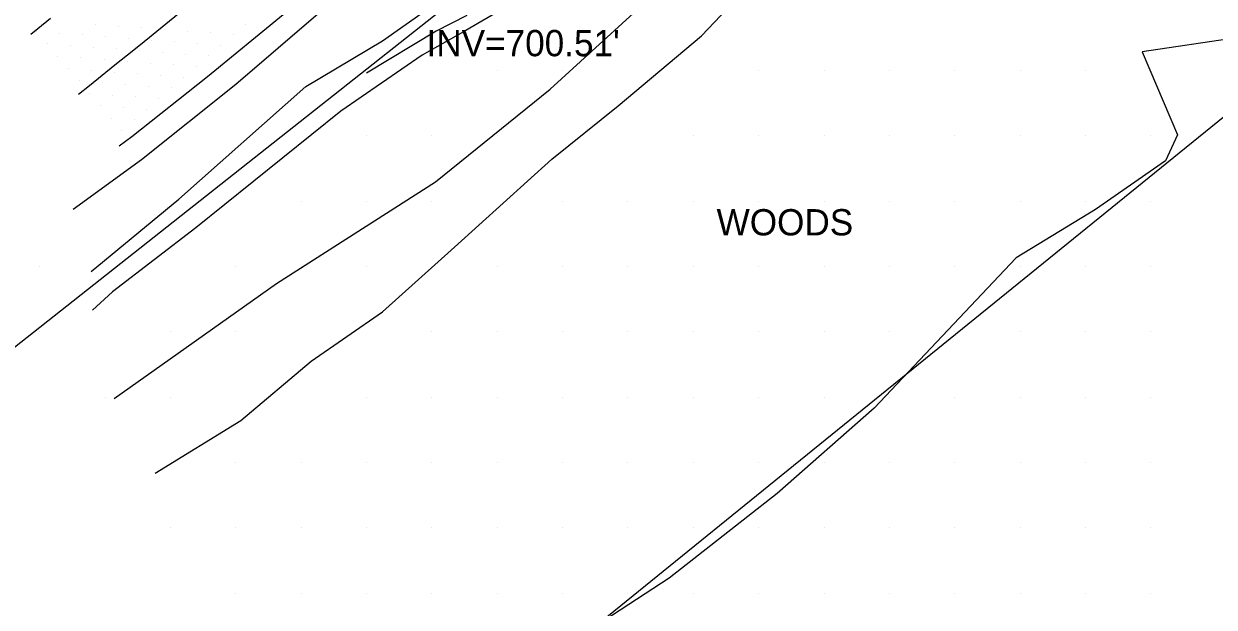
# Model space of a CAD drawing. Extents: x 1548934 to 1561348, y 809680 to 824075.
# Drawn here: x 1551457.5 to 1551639.7, y 810277.8 to 810367.1 of the extents above; entities that cross this region are included whole.
import ezdxf

# ---------------------------------------------------------------- set-up
doc = ezdxf.new("R2010")
doc.units = 0
for name, color, linetype in [('E_NCDOT_Vertical_Profile_Ground_Line', 7, 'Continuous'), ('Exist DTM QL2 LIDAR Elevation Point', 7, 'Continuous'), ('Exist DTM Scan Elevation Point', 7, 'Continuous'), ('Exist Structure Minor Pipes RCP 24 Inch Invert Elevation', 7, 'Continuous'), ('Exist Vegetation Woods Line', 7, 'Continuous'), ('Exist Vegetation Woods Line Text', 7, 'Continuous'), ('P_RDY_Dimension_Text', 7, 'Continuous'), ('P_RDY_Lane_Line', 7, 'Continuous'), ('P_RDY_Terminator_Cell', 7, 'Continuous'), ('PH Exist DTM Breakline', 7, 'Continuous')]:
    doc.layers.add(name, color=color, linetype=linetype)

msp = doc.modelspace()

# ---------------------------------------------------------------- linework, layer by layer
at = {"layer": 'E_NCDOT_Vertical_Profile_Ground_Line'}
msp.add_lwpolyline([(1551472.11, 810348.46), (1551474.03, 810349.86), (1551485.64, 810359.04), (1551508.8, 810378.11), (1551532.17, 810396.94), (1551555.37, 810415.98), (1551578.48, 810435.11), (1551601.47, 810454.39), (1551624.77, 810473.31), (1551647.83, 810492.49), (1551655.17, 810499.15), (1551678.16, 810518.43), (1551701.2, 810537.64), (1551724, 810557.15), (1551746.83, 810576.6), (1551761.53, 810588.98)], dxfattribs=at)
at = {"layer": 'Exist DTM QL2 LIDAR Elevation Point'}
for p, q in [((1551529.98, 810359.96), (1551529.98, 810359.96)), ((1551539.98, 810359.96), (1551539.98, 810359.96)), ((1551569.98, 810359.96), (1551569.98, 810359.96)), ((1551579.99, 810359.96), (1551579.99, 810359.96)), ((1551589.99, 810359.96), (1551589.99, 810359.96)), ((1551599.99, 810359.96), (1551599.99, 810359.96)), ((1551609.99, 810359.96), (1551609.99, 810359.96)), ((1551619.99, 810359.96), (1551619.99, 810359.96)), ((1551629.99, 810359.96), (1551629.99, 810359.96)), ((1551509.98, 810349.96), (1551509.98, 810349.96)), ((1551519.98, 810349.96), (1551519.98, 810349.96)), ((1551529.98, 810349.96), (1551529.98, 810349.96)), ((1551559.98, 810349.96), (1551559.98, 810349.96)), ((1551569.98, 810349.96), (1551569.98, 810349.96)), ((1551579.99, 810349.96), (1551579.99, 810349.96)), ((1551589.99, 810349.96), (1551589.99, 810349.96)), ((1551599.99, 810349.96), (1551599.99, 810349.96)), ((1551609.99, 810349.96), (1551609.99, 810349.96)), ((1551619.99, 810349.96), (1551619.99, 810349.96)), ((1551629.99, 810349.96), (1551629.99, 810349.96)), ((1551499.98, 810339.96), (1551499.98, 810339.96)), ((1551509.98, 810339.96), (1551509.98, 810339.96)), ((1551519.98, 810339.96), (1551519.98, 810339.96)), ((1551539.98, 810339.96), (1551539.98, 810339.96)), ((1551549.98, 810339.96), (1551549.98, 810339.96)), ((1551559.98, 810339.96), (1551559.98, 810339.96)), ((1551569.98, 810339.96), (1551569.98, 810339.96)), ((1551579.99, 810339.96), (1551579.99, 810339.96)), ((1551589.99, 810339.96), (1551589.99, 810339.96)), ((1551599.99, 810339.96), (1551599.99, 810339.96)), ((1551609.99, 810339.96), (1551609.99, 810339.96)), ((1551619.99, 810339.96), (1551619.99, 810339.96)), ((1551629.99, 810339.96), (1551629.99, 810339.96)), ((1551459.98, 810329.96), (1551459.98, 810329.96)), ((1551489.98, 810329.96), (1551489.98, 810329.96)), ((1551499.98, 810329.96), (1551499.98, 810329.96)), ((1551509.98, 810329.96), (1551509.98, 810329.96)), ((1551529.98, 810329.96), (1551529.98, 810329.96)), ((1551539.98, 810329.96), (1551539.98, 810329.96)), ((1551549.98, 810329.96), (1551549.98, 810329.96)), ((1551559.98, 810329.96), (1551559.98, 810329.96)), ((1551569.98, 810329.96), (1551569.98, 810329.96)), ((1551579.99, 810329.96), (1551579.99, 810329.96)), ((1551589.99, 810329.96), (1551589.99, 810329.96)), ((1551599.99, 810329.96), (1551599.99, 810329.96)), ((1551609.99, 810329.96), (1551609.99, 810329.96)), ((1551619.99, 810329.96), (1551619.99, 810329.96)), ((1551629.99, 810329.96), (1551629.99, 810329.96)), ((1551459.98, 810319.96), (1551459.98, 810319.96)), ((1551479.98, 810319.96), (1551479.98, 810319.96)), ((1551489.98, 810319.96), (1551489.98, 810319.96)), ((1551519.98, 810319.96), (1551519.98, 810319.96)), ((1551529.98, 810319.96), (1551529.98, 810319.96)), ((1551539.98, 810319.96), (1551539.98, 810319.96)), ((1551549.98, 810319.96), (1551549.98, 810319.96)), ((1551559.98, 810319.96), (1551559.98, 810319.96)), ((1551569.98, 810319.96), (1551569.98, 810319.96)), ((1551579.99, 810319.96), (1551579.99, 810319.96)), ((1551589.99, 810319.96), (1551589.99, 810319.96)), ((1551599.99, 810319.96), (1551599.99, 810319.96)), ((1551609.99, 810319.96), (1551609.99, 810319.96)), ((1551619.99, 810319.96), (1551619.99, 810319.96)), ((1551629.99, 810319.96), (1551629.99, 810319.96)), ((1551469.98, 810309.96), (1551469.98, 810309.96)), ((1551479.98, 810309.96), (1551479.98, 810309.96)), ((1551509.98, 810309.96), (1551509.98, 810309.96)), ((1551519.98, 810309.96), (1551519.98, 810309.96)), ((1551529.98, 810309.96), (1551529.98, 810309.96)), ((1551539.98, 810309.96), (1551539.98, 810309.96)), ((1551549.98, 810309.96), (1551549.98, 810309.96)), ((1551559.98, 810309.96), (1551559.98, 810309.96)), ((1551569.98, 810309.96), (1551569.98, 810309.96)), ((1551579.99, 810309.96), (1551579.99, 810309.96)), ((1551589.99, 810309.96), (1551589.99, 810309.96)), ((1551599.99, 810309.96), (1551599.99, 810309.96)), ((1551609.99, 810309.96), (1551609.99, 810309.96)), ((1551619.99, 810309.96), (1551619.99, 810309.96)), ((1551629.99, 810309.96), (1551629.99, 810309.96)), ((1551489.98, 810299.96), (1551489.98, 810299.96)), ((1551499.98, 810299.96), (1551499.98, 810299.96)), ((1551509.98, 810299.96), (1551509.98, 810299.96)), ((1551519.98, 810299.96), (1551519.98, 810299.96)), ((1551529.98, 810299.96), (1551529.98, 810299.96)), ((1551539.98, 810299.96), (1551539.98, 810299.96)), ((1551549.98, 810299.96), (1551549.98, 810299.96)), ((1551559.98, 810299.96), (1551559.98, 810299.96)), ((1551569.98, 810299.96), (1551569.98, 810299.96)), ((1551579.99, 810299.96), (1551579.99, 810299.96)), ((1551589.99, 810299.96), (1551589.99, 810299.96)), ((1551599.99, 810299.96), (1551599.99, 810299.96)), ((1551609.99, 810299.96), (1551609.99, 810299.96)), ((1551619.99, 810299.96), (1551619.99, 810299.96)), ((1551629.99, 810299.96), (1551629.99, 810299.96)), ((1551479.98, 810289.95), (1551479.98, 810289.95)), ((1551489.98, 810289.95), (1551489.98, 810289.95)), ((1551499.98, 810289.95), (1551499.98, 810289.95)), ((1551509.98, 810289.95), (1551509.98, 810289.95)), ((1551519.98, 810289.95), (1551519.98, 810289.95)), ((1551529.98, 810289.95), (1551529.98, 810289.95)), ((1551539.98, 810289.95), (1551539.98, 810289.95)), ((1551549.98, 810289.95), (1551549.98, 810289.95)), ((1551559.98, 810289.95), (1551559.98, 810289.95)), ((1551569.98, 810289.95), (1551569.98, 810289.95)), ((1551579.99, 810289.95), (1551579.99, 810289.95)), ((1551589.99, 810289.95), (1551589.99, 810289.95)), ((1551599.99, 810289.95), (1551599.99, 810289.95)), ((1551609.99, 810289.95), (1551609.99, 810289.95)), ((1551619.99, 810289.95), (1551619.99, 810289.95)), ((1551629.99, 810289.95), (1551629.99, 810289.95)), ((1551489.98, 810279.95), (1551489.98, 810279.95)), ((1551499.98, 810279.95), (1551499.98, 810279.95)), ((1551509.98, 810279.95), (1551509.98, 810279.95)), ((1551519.98, 810279.95), (1551519.98, 810279.95)), ((1551529.98, 810279.95), (1551529.98, 810279.95)), ((1551539.98, 810279.95), (1551539.98, 810279.95)), ((1551549.98, 810279.95), (1551549.98, 810279.95)), ((1551559.98, 810279.95), (1551559.98, 810279.95)), ((1551569.98, 810279.95), (1551569.98, 810279.95)), ((1551579.99, 810279.95), (1551579.99, 810279.95)), ((1551589.99, 810279.95), (1551589.99, 810279.95)), ((1551599.99, 810279.95), (1551599.99, 810279.95)), ((1551609.99, 810279.95), (1551609.99, 810279.95)), ((1551619.99, 810279.95), (1551619.99, 810279.95)), ((1551629.99, 810279.95), (1551629.99, 810279.95))]:
    msp.add_line(p, q, dxfattribs=at)
at = {"layer": 'Exist DTM Scan Elevation Point'}
for p, q in [((1551468.44, 810367.06), (1551468.44, 810367.06)), ((1551471.96, 810366.79), (1551471.96, 810366.79)), ((1551475.49, 810366.53), (1551475.49, 810366.53)), ((1551479.01, 810366.26), (1551479.01, 810366.26)), ((1551491.49, 810367.09), (1551491.49, 810367.09)), ((1551459.49, 810365.97), (1551459.49, 810365.97)), ((1551463.01, 810365.7), (1551463.01, 810365.7)), ((1551466.54, 810365.43), (1551466.54, 810365.43)), ((1551470.07, 810365.17), (1551470.07, 810365.17)), ((1551473.59, 810364.9), (1551473.59, 810364.9)), ((1551477.12, 810364.63), (1551477.12, 810364.63)), ((1551482.54, 810365.99), (1551482.54, 810365.99)), ((1551486.06, 810365.73), (1551486.06, 810365.73)), ((1551489.59, 810365.46), (1551489.59, 810365.46)), ((1551461.12, 810364.07), (1551461.12, 810364.07)), ((1551464.64, 810363.8), (1551464.64, 810363.8)), ((1551468.17, 810363.54), (1551468.17, 810363.54)), ((1551471.69, 810363.27), (1551471.69, 810363.27)), ((1551475.22, 810363), (1551475.22, 810363)), ((1551478.75, 810362.73), (1551478.75, 810362.73)), ((1551480.64, 810364.36), (1551480.64, 810364.36)), ((1551484.17, 810364.1), (1551484.17, 810364.1)), ((1551487.69, 810363.83), (1551487.69, 810363.83)), ((1551462.75, 810362.18), (1551462.75, 810362.18)), ((1551466.27, 810361.91), (1551466.27, 810361.91)), ((1551469.8, 810361.64), (1551469.8, 810361.64)), ((1551473.32, 810361.37), (1551473.32, 810361.37)), ((1551476.85, 810361.11), (1551476.85, 810361.11)), ((1551480.37, 810360.84), (1551480.37, 810360.84)), ((1551482.27, 810362.47), (1551482.27, 810362.47)), ((1551485.8, 810362.2), (1551485.8, 810362.2)), ((1551464.38, 810360.28), (1551464.38, 810360.28)), ((1551467.9, 810360.01), (1551467.9, 810360.01)), ((1551471.43, 810359.74), (1551471.43, 810359.74)), ((1551474.95, 810359.48), (1551474.95, 810359.48)), ((1551478.48, 810359.21), (1551478.48, 810359.21)), ((1551483.9, 810360.57), (1551483.9, 810360.57)), ((1551466.01, 810358.38), (1551466.01, 810358.38)), ((1551469.53, 810358.12), (1551469.53, 810358.12)), ((1551473.06, 810357.85), (1551473.06, 810357.85)), ((1551476.58, 810357.58), (1551476.58, 810357.58)), ((1551480.11, 810357.31), (1551480.11, 810357.31)), ((1551482, 810358.94), (1551482, 810358.94)), ((1551467.63, 810356.49), (1551467.63, 810356.49)), ((1551471.16, 810356.22), (1551471.16, 810356.22)), ((1551474.69, 810355.95), (1551474.69, 810355.95)), ((1551478.21, 810355.68), (1551478.21, 810355.68)), ((1551469.26, 810354.59), (1551469.26, 810354.59)), ((1551472.79, 810354.32), (1551472.79, 810354.32)), ((1551476.32, 810354.06), (1551476.32, 810354.06)), ((1551470.89, 810352.69), (1551470.89, 810352.69)), ((1551474.42, 810352.43), (1551474.42, 810352.43)), ((1551472.52, 810350.8), (1551472.52, 810350.8))]:
    msp.add_line(p, q, dxfattribs=at)
at = {"layer": 'Exist Vegetation Woods Line'}
for points in [[(1551471.33, 810309.76), (1551496.19, 810327.35), (1551520.55, 810342.93), (1551538.1, 810357.1), (1551563.58, 810380.42), (1551579.64, 810396.97), (1551595.16, 810410.86), (1551619.57, 810437), (1551642.9, 810456.37), (1551671.93, 810478.9)], [(1551704.06, 810393.24), (1551690.95, 810387.37), (1551677.59, 810377.87), (1551667.65, 810369.78), (1551659.37, 810366.8), (1551650.36, 810361.59), (1551643.13, 810364.98), (1551628.69, 810362.84), (1551634.09, 810350.14), (1551632.23, 810346.13), (1551621.54, 810338.68), (1551609.38, 810331.29), (1551587.67, 810308.27), (1551572.84, 810295.21), (1551556.27, 810282.23), (1551533.93, 810267.67), (1551517.37, 810252.68)]]:
    msp.add_lwpolyline(points, dxfattribs=at)
at = {"layer": 'P_RDY_Dimension_Text'}
msp.add_lwpolyline([(1551859.71, 810539.41), (1551760.08, 810452.75), (1551665.88, 810372.94), (1551515.48, 810250.92)], dxfattribs=at)
at = {"layer": 'P_RDY_Lane_Line'}
msp.add_lwpolyline([(1551524.36, 810371.57), (1551217.25, 810128.83)], dxfattribs=at)
at = {"layer": 'P_RDY_Terminator_Cell'}
for points in [[(1551481.18, 810368.63), (1551479.24, 810367.05), (1551477.3, 810365.47), (1551475.36, 810363.9), (1551473.41, 810362.33), (1551471.46, 810360.77), (1551469.51, 810359.2), (1551467.56, 810357.64), (1551465.9, 810356.31)], [(1551458.6, 810365.56), (1551459.68, 810366.43), (1551461.62, 810368)]]:
    msp.add_lwpolyline(points, dxfattribs=at)
at = {"layer": 'PH Exist DTM Breakline'}
for points in [[(1551677.8, 810514.19), (1551668.56, 810505.95), (1551658.21, 810497.26), (1551646.7, 810487.22), (1551632.51, 810476.45), (1551621.41, 810466.65), (1551610.48, 810457.6), (1551596.92, 810445.81), (1551580.66, 810432.76), (1551566.85, 810420.92), (1551558.92, 810413.49), (1551545.19, 810402.75), (1551535.64, 810395.97), (1551528.32, 810389.69), (1551515.65, 810379.06), (1551502.94, 810368.97), (1551489.96, 810357.83), (1551475.53, 810346.28), (1551465.06, 810338.7)], [(1551477.62, 810298.3), (1551490.74, 810306.41), (1551501.52, 810315.49), (1551512.44, 810323.02), (1551523.43, 810332.94), (1551538.32, 810346.42), (1551548.49, 810354.56), (1551561.25, 810365.28), (1551570.99, 810375.62), (1551593.88, 810390.41), (1551601.53, 810396.72), (1551614.89, 810407.77), (1551625.58, 810416.03), (1551632.63, 810422.48), (1551651.47, 810436.29), (1551670.78, 810450.45), (1551699.84, 810472.96)], [(1551650.95, 810468.89), (1551639.86, 810460.4), (1551630.02, 810451.07), (1551617.78, 810440.45), (1551604.79, 810429.5), (1551595.01, 810420.43), (1551584.7, 810411.11), (1551576.14, 810404.97), (1551562.29, 810391.71), (1551551.75, 810382.86), (1551542.15, 810376.06), (1551525.19, 810366.11), (1551518.5, 810362.33), (1551506.04, 810353.73), (1551483.86, 810335.87), (1551471.09, 810326.11), (1551468.02, 810323.27)], [(1551467.81, 810329.19), (1551481.27, 810340.28), (1551500.67, 810357.53), (1551512.41, 810364.53), (1551518.29, 810368.64), (1551522.28, 810371.67)], [(1551525.32, 810368.38), (1551520.65, 810366.02), (1551509.97, 810359.56)]]:
    msp.add_lwpolyline(points, dxfattribs=at)

# ---------------------------------------------------------------- texts
at = {"layer": 'Exist Structure Minor Pipes RCP 24 Inch Invert Elevation'}
msp.add_text("INV=700.51'", height=4.02, rotation=360, dxfattribs=at).set_placement((1551519.16, 810362.16))
at = {"layer": 'Exist Vegetation Woods Line Text'}
msp.add_text('WOODS', height=4.02, dxfattribs=at).set_placement((1551563.55, 810334.73))

doc.saveas('drawing.dxf')
